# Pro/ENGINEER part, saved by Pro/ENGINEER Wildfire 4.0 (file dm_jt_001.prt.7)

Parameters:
  METRIC = "NO"

Other parameters: PITCH, DRILL_DIAMETER, THREAD_DIAMETER, THREADS_PER_INCH, THREAD_DEPTH, THREAD_LENGTH, DRILL_POINT_ANGLE, DRILL_DEPTH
